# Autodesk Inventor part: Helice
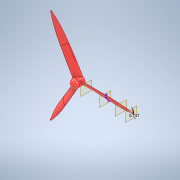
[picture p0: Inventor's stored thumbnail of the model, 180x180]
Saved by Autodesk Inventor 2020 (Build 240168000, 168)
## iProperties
Created: 2021-06
Part Number: Helice
Material: Nilón 6/6
Document SubType Name: Modeling
Designer: Sergio
Density: 1.13 g/cm^3
Appearance: Nilón 6
Author: Sergio
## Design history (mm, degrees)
sketch "Boceto2"
  geometry: C1 r 5 at (0, 0); 1 further point
  constraints: 1 centre point, 1 coincident
  dimensions: "d1" = 10 diameter of C1
extrude "Extrusión1" new body sketch "Boceto2" distance "d2" = 12; taper "d3" = 0 deg
sketch "Boceto3"
  geometry: C1 r 1.15 at (0, 0); 1 further point
  constraints: 1 centre point, 1 coincident
  dimensions: "d4" = 2.3 diameter of C1
hole "Agujero1" sketch "Boceto3" at (0, 0) diameter "d5" = 2.3; stored, may be unused: countersink angle "d9" = 90 deg, drill point angle "d11" = 0 deg; dims "d6" = 6, "d7" = 4, "d8" = 2, "d10" = 5
fillet "Empalme1" dims "d12" = 5
node "Plano de trabajo1"
sketch "Boceto7"
  geometry: L1 (-3.874, 0.044)-(-2.942, 0.044); 5 further points
  constraints: 2 end point, 1 horizontal, 7 other
node "Plano de trabajo4"
sketch "Boceto11"
  geometry: L1 (5, 0)-(-5, 0) reference; 6 further points
  constraints: 1 point on line, 7 other
node "Plano de trabajo5"
sketch "Boceto12"
  geometry: 5 further points
  constraints: 7 other
node "Plano de trabajo6"
node "Plano de trabajo7"
sketch "Boceto14" dims "d51" = 0.71678
  geometry: 2 further points; 1 other entity
  constraints: 2 other
feature "Solevación1" dims "d21" = 0, "d22" = 90 deg, "d23" = 0, "d24" = 90 deg, "d31" = 0, "d32" = 90 deg
feature "Solevación3" dims "d33" = 0, "d34" = 90 deg, "d35" = 0, "d36" = 90 deg, "d47" = 0, "d48" = 90 deg
pattern_circular "Patrón circular1" dims angle "d43" = 360 deg
sketch "Boceto15" dims "d50" = 0.71678 (derived)
  geometry: L1 (-0.548, 3.704)-(-0.504, 3.539); L2 (-0.526, 3.621)-(-0.548, 3.704); 8 further points; 1 other entity
  constraints: 4 end point, 2 coincident, 1 midpoint, 10 other
revolve "Revolución1" sketch "Boceto15" stored, may be unused: angle "d49" = 180 deg
node "Sólido1"
sketch "Boceto13"
  geometry: 6 further points
  constraints: 7 other
other parameters: "d15" = 3, "d18" = 12, "d19" = 35, "d20" = 54, "d37" = 66.7832
